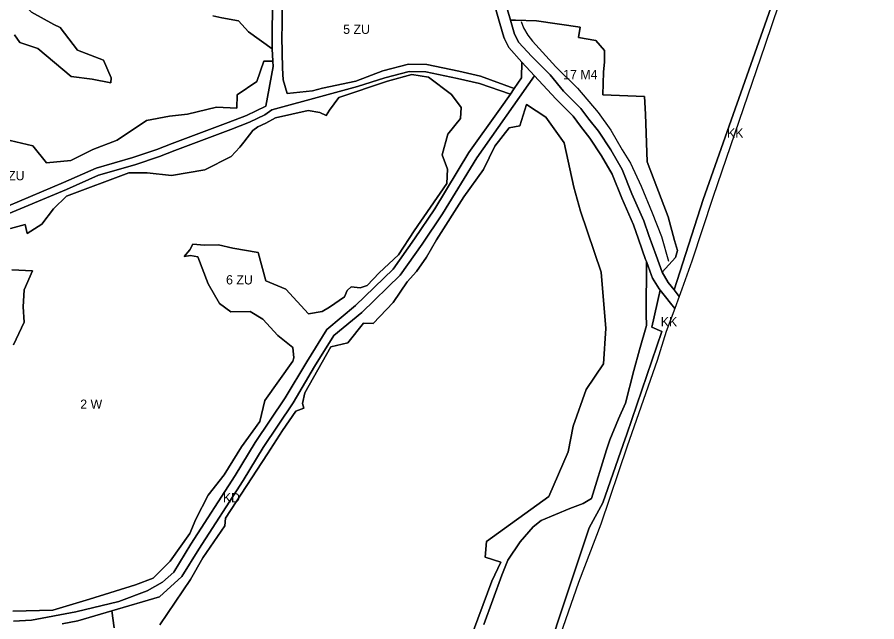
# Model space of a CAD drawing. Extents: x 7437831 to 7440315, y 5545798 to 5547888.
# Drawn here: x 7439385 to 7440315, y 5546197 to 5546851 of the extents above; entities that cross this region are included whole.
import ezdxf

# ---------------------------------------------------------------- set-up
doc = ezdxf.new("R2010")
doc.units = 0
for name, color, linetype in [('linie_rozgraniczajace', 7, 'Continuous'), ('linie_zabudowy_nieprzekraczalne', 7, 'Continuous'), ('oznaczenia_przeznaczen', 7, 'Continuous')]:
    doc.layers.add(name, color=color, linetype=linetype)

msp = doc.modelspace()

# ---------------------------------------------------------------- linework, layer by layer
at = {"layer": 'linie_rozgraniczajace'}
for points in [[(7440308.05, 5547177.94), (7440315.29, 5547171.09), (7440256.26, 5546998.43), (7440230.77, 5546929.2), (7440194.34, 5546821.2), (7440137.83, 5546655.9), (7440115.26, 5546587.11), (7440104.3, 5546556.76), (7440101.52, 5546548.77), (7440096.01, 5546555.84), (7440127.28, 5546653.58), (7440200.75, 5546860.84)], [(7439918.8, 5546847.65), (7439924.22, 5546847.6), (7439947.11, 5546846.82), (7439994.18, 5546840.04), (7439992.52, 5546828.97), (7440011.09, 5546825.6), (7440020.73, 5546814.89), (7440020.47, 5546802.43), (7440019.46, 5546791.36), (7440018.71, 5546766.87), (7440064.01, 5546765.21), (7440064.91, 5546745.98), (7440066.91, 5546694.54), (7440089.6, 5546635.12), (7440096.53, 5546609.5), (7440099.68, 5546598.47), (7440097.3, 5546591.13), (7440082.84, 5546574.93), (7440076.45, 5546592.96), (7440068.57, 5546614.77), (7440063.17, 5546630.62), (7440050.2, 5546659.93), (7440039.6, 5546686.31), (7440027.44, 5546707.26), (7440014.28, 5546727.5), (7440003.83, 5546740.49), (7439995.16, 5546752.12), (7439976.38, 5546771), (7439961.64, 5546788.64), (7439941.49, 5546808.71), (7439927.82, 5546823.37), (7439923.29, 5546832.62)]]:
    msp.add_lwpolyline(points, close=True, dxfattribs=at)
for points in [[(7439486.82, 5546785.36), (7439478.44, 5546804.23), (7439450.21, 5546815.29), (7439431.59, 5546839.56), (7439424.64, 5546843.02), (7439400.36, 5546856.35), (7439385.83, 5546872.11), (7439401.24, 5546882.58), (7439408.98, 5546907.43), (7439402.67, 5546916.88), (7439385.28, 5546930.1), (7439387.21, 5546943.73), (7439385.76, 5546947.44), (7439390.7, 5546965.05)], [(7439381.22, 5546942.02), (7439385.76, 5546947.44), (7439387.21, 5546943.73), (7439385.28, 5546930.1), (7439402.67, 5546916.88), (7439408.98, 5546907.43), (7439401.24, 5546882.58), (7439385.83, 5546872.11), (7439400.36, 5546856.35), (7439424.64, 5546843.02), (7439431.59, 5546839.56), (7439450.21, 5546815.29), (7439478.44, 5546804.23), (7439486.82, 5546785.36), (7439486.23, 5546779.85), (7439466.03, 5546783.83), (7439443.54, 5546786.77), (7439407.4, 5546817.11), (7439388.08, 5546823.63), (7439382.15, 5546831.69)], [(7439363.32, 5546641.95), (7439435.2, 5546672.02), (7439470.38, 5546687.44), (7439510.11, 5546699), (7439536.19, 5546707.81), (7439552.73, 5546714.25), (7439613.29, 5546736.86), (7439633.09, 5546744.54), (7439654.12, 5546754.75), (7439662.13, 5546797.65), (7439661.78, 5546803.45), (7439661, 5546816.56), (7439661.34, 5546878.71)], [(7439671.37, 5546879.16), (7439671.77, 5546841.75), (7439671.4, 5546829.71), (7439672.18, 5546795.77), (7439673.06, 5546783.17), (7439677.12, 5546768.28), (7439704.72, 5546771.38), (7439715.53, 5546774.01), (7439751.52, 5546781.59), (7439780.57, 5546793.02), (7439808.46, 5546800.07), (7439828.33, 5546799.8), (7439863.08, 5546792.42), (7439886.49, 5546787.27), (7439922.97, 5546773.92), (7439918.72, 5546767.8), (7439885.39, 5546779.32), (7439861.38, 5546784.6), (7439827.44, 5546791.81), (7439809.4, 5546792.06), (7439782.77, 5546785.32), (7439753.23, 5546775.91), (7439717.62, 5546766.29), (7439660.5, 5546750.58), (7439653.17, 5546745.39), (7439636.29, 5546737.2), (7439616.14, 5546729.39), (7439555.58, 5546706.77), (7439538.92, 5546700.29), (7439512.51, 5546691.36), (7439473.11, 5546679.9), (7439438.35, 5546664.67), (7439366.32, 5546634.53)], [(7439661.34, 5546878.71), (7439661, 5546816.56), (7439635.43, 5546835.19), (7439624.57, 5546847.09), (7439606.57, 5546850.24), (7439596.81, 5546852.25)], [(7439903.09, 5546859.16), (7439907.31, 5546844.22), (7439911.79, 5546829.19), (7439912.51, 5546827.34), (7439917.04, 5546818.09), (7439931.02, 5546802.34), (7439930.83, 5546785.24), (7439922.97, 5546773.92), (7439886.49, 5546787.27), (7439863.08, 5546792.42), (7439828.33, 5546799.8), (7439808.46, 5546800.07), (7439780.57, 5546793.02), (7439751.52, 5546781.59), (7439715.53, 5546774.01), (7439704.72, 5546771.38), (7439677.12, 5546768.28), (7439673.06, 5546783.17), (7439672.18, 5546795.77), (7439671.4, 5546829.71), (7439671.77, 5546841.75), (7439671.37, 5546879.16)], [(7439596.81, 5546852.25), (7439606.57, 5546850.24), (7439624.57, 5546847.09), (7439635.43, 5546835.19), (7439661, 5546816.56), (7439661.78, 5546803.45), (7439651.83, 5546803.38), (7439644.33, 5546781.26), (7439623.01, 5546766.92), (7439622.81, 5546752.31), (7439600.71, 5546753.63), (7439569.33, 5546746.09), (7439549.86, 5546743.89), (7439525.1, 5546739.11), (7439493.26, 5546717.83), (7439466.82, 5546707.92), (7439443.08, 5546695.91), (7439416.71, 5546693.37), (7439401.89, 5546711.77), (7439377.63, 5546717.6)], [(7439915.58, 5546858.94), (7439918.8, 5546847.65), (7439923.29, 5546832.62), (7439927.82, 5546823.37), (7439941.49, 5546808.71), (7439961.64, 5546788.64), (7439976.38, 5546771), (7439995.16, 5546752.12), (7440003.83, 5546740.49), (7440014.28, 5546727.5), (7440027.44, 5546707.26), (7440039.6, 5546686.31), (7440050.2, 5546659.93), (7440063.17, 5546630.62), (7440068.57, 5546614.77), (7440076.45, 5546592.96), (7440082.84, 5546574.93), (7440089.68, 5546563.94), (7440096.01, 5546555.84), (7440101.52, 5546548.77), (7440096.72, 5546535.85), (7440092.06, 5546541.39), (7440086.55, 5546548.45), (7440080.94, 5546555.64), (7440079.86, 5546557.08), (7440072.65, 5546568.58), (7440071.34, 5546571.44), (7440065.9, 5546586.8), (7440065.16, 5546588.89), (7440057.29, 5546610.7), (7440051.98, 5546626.25), (7440039.23, 5546655.08), (7440028.79, 5546681.04), (7440017.21, 5546700.97), (7440004.88, 5546719.95), (7439994.49, 5546732.96), (7439986.65, 5546743.66), (7439967.87, 5546762.54), (7439944.92, 5546787.32), (7439931.02, 5546802.34), (7439917.04, 5546818.09), (7439912.51, 5546827.34), (7439911.79, 5546829.19), (7439907.31, 5546844.22), (7439903.09, 5546859.16)], [(7440200.75, 5546860.84), (7440127.28, 5546653.58), (7440096.01, 5546555.84), (7440089.68, 5546563.94), (7440082.84, 5546574.93), (7440097.3, 5546591.13), (7440099.68, 5546598.47), (7440096.53, 5546609.5), (7440089.6, 5546635.12), (7440066.91, 5546694.54), (7440064.91, 5546745.98), (7440064.01, 5546765.21), (7440018.71, 5546766.87), (7440019.46, 5546791.36), (7440020.47, 5546802.43), (7440020.73, 5546814.89), (7440011.09, 5546825.6), (7439992.52, 5546828.97), (7439994.18, 5546840.04), (7439947.11, 5546846.82), (7439924.22, 5546847.6), (7439918.8, 5546847.65), (7439915.58, 5546858.94)], [(7439382.15, 5546831.69), (7439388.08, 5546823.63), (7439407.4, 5546817.11), (7439443.54, 5546786.77), (7439466.03, 5546783.83), (7439486.23, 5546779.85), (7439486.82, 5546785.36)], [(7439377.63, 5546717.6), (7439401.89, 5546711.77), (7439416.71, 5546693.37), (7439443.08, 5546695.91), (7439466.82, 5546707.92), (7439493.26, 5546717.83), (7439525.1, 5546739.11), (7439549.86, 5546743.89), (7439569.33, 5546746.09), (7439600.71, 5546753.63), (7439622.81, 5546752.31), (7439623.01, 5546766.92), (7439644.33, 5546781.26), (7439651.83, 5546803.38), (7439661.78, 5546803.45), (7439662.13, 5546797.65), (7439654.12, 5546754.75), (7439633.09, 5546744.54), (7439613.29, 5546736.86), (7439552.73, 5546714.25), (7439536.19, 5546707.81), (7439510.11, 5546699), (7439470.38, 5546687.44), (7439435.2, 5546672.02), (7439363.32, 5546641.95)], [(7439380.94, 5546197.47), (7439400.62, 5546198.75), (7439448.52, 5546207.84), (7439495.02, 5546219.05), (7439525.63, 5546230.47), (7439542.17, 5546239.93), (7439554.55, 5546250.62), (7439573.14, 5546280.84), (7439621.09, 5546355.07), (7439642.72, 5546390.77), (7439675.08, 5546439.03), (7439698.39, 5546478.28), (7439720.08, 5546513.24), (7439751.29, 5546539.09), (7439792.03, 5546578.22), (7439814.95, 5546611.06), (7439836.9, 5546643.49), (7439873.96, 5546704.41), (7439907.41, 5546751.52), (7439918.72, 5546767.8), (7439922.97, 5546773.92), (7439930.83, 5546785.24), (7439931.02, 5546802.34), (7439944.92, 5546787.32), (7439882.31, 5546698.91), (7439845.31, 5546638.09), (7439823.19, 5546605.4), (7439799.67, 5546571.7), (7439757.95, 5546531.62), (7439727.72, 5546506.58), (7439706.94, 5546473.09), (7439683.54, 5546433.69), (7439651.15, 5546385.39), (7439629.56, 5546349.77), (7439581.6, 5546275.5), (7439563.31, 5546245.78), (7439539.14, 5546224.11), (7439487.44, 5546208.89), (7439450.62, 5546198.06), (7439433.75, 5546194.86)], [(7439366.32, 5546634.53), (7439438.35, 5546664.67), (7439473.11, 5546679.9), (7439512.51, 5546691.36), (7439538.92, 5546700.29), (7439555.58, 5546706.77), (7439616.14, 5546729.39), (7439636.29, 5546737.2), (7439653.17, 5546745.39), (7439660.5, 5546750.58), (7439717.62, 5546766.29), (7439753.23, 5546775.91), (7439782.77, 5546785.32), (7439809.4, 5546792.06), (7439827.44, 5546791.81), (7439861.38, 5546784.6), (7439885.39, 5546779.32), (7439918.72, 5546767.8), (7439907.41, 5546751.52), (7439873.96, 5546704.41), (7439836.9, 5546643.49), (7439814.95, 5546611.06), (7439792.03, 5546578.22), (7439751.29, 5546539.09), (7439720.08, 5546513.24), (7439698.39, 5546478.28), (7439675.08, 5546439.03), (7439642.72, 5546390.77), (7439621.09, 5546355.07), (7439573.14, 5546280.84), (7439554.55, 5546250.62), (7439542.17, 5546239.93), (7439525.63, 5546230.47), (7439495.02, 5546219.05), (7439448.52, 5546207.84), (7439400.62, 5546198.75), (7439380.94, 5546197.47)], [(7439854.94, 5546767.31), (7439829.99, 5546786.14), (7439812.14, 5546788.85), (7439785.73, 5546781.58), (7439733.11, 5546763.89), (7439723.11, 5546750.4), (7439719.31, 5546744.42), (7439712.48, 5546747.88), (7439700.05, 5546749.8), (7439664.46, 5546742.01), (7439654.25, 5546736.22), (7439645.44, 5546732.23), (7439640.09, 5546728.4), (7439630.22, 5546715.54), (7439625.85, 5546710.21), (7439616.78, 5546700.12), (7439588.12, 5546685.96), (7439552.05, 5546679.57), (7439525.86, 5546682.66), (7439506.01, 5546682.43), (7439438.29, 5546657.31), (7439424.49, 5546643.76), (7439411.74, 5546627.05), (7439395.98, 5546616.82), (7439393.73, 5546626.76), (7439377.82, 5546622.48)], [(7439654.25, 5546736.22), (7439664.46, 5546742.01), (7439700.05, 5546749.8), (7439712.48, 5546747.88), (7439719.31, 5546744.42), (7439723.11, 5546750.4), (7439733.11, 5546763.89), (7439785.73, 5546781.58), (7439812.14, 5546788.85), (7439829.99, 5546786.14), (7439854.94, 5546767.31), (7439865.39, 5546753.05), (7439864.65, 5546741.39), (7439850.93, 5546724.3), (7439844.77, 5546702), (7439850.54, 5546686.56), (7439849.95, 5546670.96), (7439814.52, 5546619.84), (7439797.76, 5546593.98), (7439776.69, 5546574.39), (7439763.82, 5546560.75), (7439756.21, 5546558.2), (7439746.55, 5546559.29), (7439742.26, 5546555.36), (7439739.41, 5546548.45), (7439723, 5546537.34), (7439715.03, 5546532.67), (7439700.14, 5546530.18), (7439675.72, 5546556.88), (7439654.05, 5546565.6), (7439645.85, 5546596.41), (7439618.28, 5546601.15), (7439603, 5546604.77), (7439587.65, 5546604.19), (7439575.25, 5546605.29), (7439571.74, 5546599.27), (7439565.85, 5546592.14), (7439572.75, 5546593.24), (7439580.43, 5546591.53), (7439591.85, 5546562.44), (7439603.95, 5546541.22), (7439616.1, 5546532.37), (7439637.28, 5546532.49), (7439650.84, 5546524.37), (7439666.99, 5546506.61), (7439683.27, 5546493.77), (7439684.46, 5546482.5), (7439683.29, 5546478.67), (7439653.2, 5546436.29), (7439647.48, 5546413.73), (7439627.89, 5546386.15), (7439608.9, 5546355.91), (7439591.6, 5546334.01), (7439578.21, 5546307.89), (7439571.85, 5546292.55), (7439550.5, 5546262.35), (7439532.26, 5546243.99), (7439513.25, 5546237), (7439463.2, 5546221.29), (7439423.56, 5546209.6), (7439380.47, 5546208.46)], [(7439490.15, 5546190.37), (7439487.44, 5546208.89), (7439539.14, 5546224.11), (7439563.31, 5546245.78), (7439581.6, 5546275.5), (7439629.56, 5546349.77), (7439651.15, 5546385.39), (7439683.54, 5546433.69), (7439706.94, 5546473.09), (7439727.72, 5546506.58), (7439757.95, 5546531.62), (7439799.67, 5546571.7), (7439823.19, 5546605.4), (7439845.31, 5546638.09), (7439882.31, 5546698.91), (7439944.92, 5546787.32), (7439967.87, 5546762.54), (7439986.65, 5546743.66), (7439994.49, 5546732.96), (7440004.88, 5546719.95), (7440017.21, 5546700.97), (7440028.79, 5546681.04), (7440039.23, 5546655.08), (7440051.98, 5546626.25), (7440057.29, 5546610.7), (7440065.16, 5546588.89), (7440065.9, 5546586.8), (7440065.64, 5546529.24), (7440066.09, 5546517.44), (7440058.48, 5546491.13), (7440052.26, 5546468.9), (7440043.46, 5546433.25), (7440035.75, 5546416.29), (7440026.32, 5546393.84), (7440022.68, 5546382.78), (7440006.48, 5546330.28), (7439997.59, 5546324.73), (7439982.99, 5546319.3), (7439952.11, 5546306.67), (7439943.44, 5546299.82), (7439929.41, 5546283.59), (7439915.91, 5546263.73), (7439909.44, 5546247.36), (7439890.04, 5546194.08)], [(7439380.47, 5546208.46), (7439423.56, 5546209.6), (7439463.2, 5546221.29), (7439513.25, 5546237), (7439532.26, 5546243.99), (7439550.5, 5546262.35), (7439571.85, 5546292.55), (7439578.21, 5546307.89), (7439591.6, 5546334.01), (7439608.9, 5546355.91), (7439627.89, 5546386.15), (7439647.48, 5546413.73), (7439653.2, 5546436.29), (7439683.29, 5546478.67), (7439684.46, 5546482.5), (7439683.27, 5546493.77), (7439666.99, 5546506.61), (7439650.84, 5546524.37), (7439637.28, 5546532.49), (7439616.1, 5546532.37), (7439603.95, 5546541.22), (7439591.85, 5546562.44), (7439580.43, 5546591.53), (7439572.75, 5546593.24), (7439565.85, 5546592.14), (7439571.74, 5546599.27), (7439575.25, 5546605.29), (7439587.65, 5546604.19), (7439603, 5546604.77), (7439618.28, 5546601.15), (7439645.85, 5546596.41), (7439654.05, 5546565.6), (7439675.72, 5546556.88), (7439700.14, 5546530.18), (7439715.03, 5546532.67), (7439723, 5546537.34), (7439739.41, 5546548.45), (7439742.26, 5546555.36), (7439746.55, 5546559.29), (7439756.21, 5546558.2), (7439763.82, 5546560.75), (7439776.69, 5546574.39), (7439797.76, 5546593.98), (7439814.52, 5546619.84), (7439849.95, 5546670.96), (7439850.54, 5546686.56), (7439844.77, 5546702), (7439850.93, 5546724.3), (7439864.65, 5546741.39), (7439865.39, 5546753.05), (7439854.94, 5546767.31)], [(7439936.27, 5546756.48), (7439929, 5546733.23), (7439917.5, 5546731.3), (7439902.1, 5546711.37), (7439889.72, 5546686.22), (7439868.39, 5546656.55), (7439838.88, 5546610.11), (7439827.86, 5546591.28), (7439817.11, 5546575.85), (7439807.17, 5546564.5), (7439792.08, 5546542.23), (7439770.26, 5546519.49), (7439759.83, 5546519.96), (7439743, 5546498.56), (7439724.61, 5546494.41), (7439696.47, 5546444.65), (7439693.93, 5546433.16), (7439695.32, 5546427.89), (7439686.58, 5546424.93), (7439672.06, 5546403.86), (7439655.91, 5546378.67), (7439610.32, 5546309.18), (7439609.75, 5546300.73), (7439585.86, 5546266.14), (7439572.52, 5546242.78), (7439539.47, 5546193.7)], [(7439936.27, 5546756.48), (7439957.3, 5546742.71), (7439976.97, 5546715.12), (7439987.59, 5546667.07), (7439994.76, 5546640.93), (7440016.97, 5546575.06), (7440021.88, 5546514.27), (7440019.37, 5546476.05), (7440000.66, 5546448.3), (7439986.83, 5546408.43), (7439981.12, 5546380.88), (7439960.5, 5546332.44), (7439892.91, 5546283.88), (7439891.56, 5546267), (7439908.37, 5546261.42), (7439898.74, 5546241.04), (7439874.23, 5546174.75)], [(7439902.1, 5546711.37), (7439917.5, 5546731.3), (7439929, 5546733.23), (7439936.27, 5546756.48)], [(7439987.59, 5546667.07), (7439976.97, 5546715.12), (7439957.3, 5546742.71), (7439936.27, 5546756.48)], [(7439377.82, 5546622.48), (7439393.73, 5546626.76), (7439395.98, 5546616.82), (7439411.74, 5546627.05), (7439424.49, 5546643.76), (7439438.29, 5546657.31), (7439506.01, 5546682.43), (7439525.86, 5546682.66), (7439552.05, 5546679.57), (7439588.12, 5546685.96), (7439616.78, 5546700.12), (7439625.85, 5546710.21), (7439630.22, 5546715.54), (7439640.09, 5546728.4), (7439645.44, 5546732.23), (7439654.25, 5546736.22)], [(7439539.47, 5546193.7), (7439572.52, 5546242.78), (7439585.86, 5546266.14), (7439609.75, 5546300.73), (7439610.32, 5546309.18), (7439655.91, 5546378.67), (7439672.06, 5546403.86), (7439686.58, 5546424.93), (7439695.32, 5546427.89), (7439693.93, 5546433.16), (7439696.47, 5546444.65), (7439724.61, 5546494.41), (7439743, 5546498.56), (7439759.83, 5546519.96), (7439770.26, 5546519.49), (7439792.08, 5546542.23), (7439807.17, 5546564.5), (7439817.11, 5546575.85), (7439827.86, 5546591.28), (7439838.88, 5546610.11), (7439868.39, 5546656.55), (7439889.72, 5546686.22), (7439902.1, 5546711.37)], [(7439874.23, 5546174.75), (7439898.74, 5546241.04), (7439908.37, 5546261.42), (7439891.56, 5546267), (7439892.91, 5546283.88), (7439960.5, 5546332.44), (7439981.12, 5546380.88), (7439986.83, 5546408.43), (7440000.66, 5546448.3), (7440019.37, 5546476.05), (7440021.88, 5546514.27), (7440016.97, 5546575.06), (7439994.76, 5546640.93), (7439987.59, 5546667.07)], [(7440065.9, 5546586.8), (7440071.34, 5546571.44), (7440072.65, 5546568.58), (7440079.86, 5546557.08), (7440080.94, 5546555.64), (7440071.86, 5546515.79), (7440082.67, 5546510.79), (7440044.68, 5546400.01), (7440040.64, 5546388.84), (7440018.65, 5546325.46), (7440004.11, 5546298.64), (7440003.11, 5546295.44), (7439970.26, 5546197.06), (7439927.82, 5546065.29)], [(7439982.99, 5546319.3), (7439997.59, 5546324.73), (7440006.48, 5546330.28), (7440022.68, 5546382.78), (7440026.32, 5546393.84), (7440035.75, 5546416.29), (7440043.46, 5546433.25), (7440052.26, 5546468.9), (7440058.48, 5546491.13), (7440066.09, 5546517.44), (7440065.64, 5546529.24), (7440065.9, 5546586.8)], [(7439379.25, 5546577.57), (7439401.45, 5546576.44), (7439392.44, 5546556.16), (7439391.49, 5546537.66), (7439392.56, 5546521.09), (7439380.9, 5546496.43)], [(7439380.9, 5546496.43), (7439392.56, 5546521.09), (7439391.49, 5546537.66), (7439392.44, 5546556.16), (7439401.45, 5546576.44), (7439379.25, 5546577.57)], [(7439927.82, 5546065.29), (7439970.26, 5546197.06), (7440003.11, 5546295.44), (7440004.11, 5546298.64), (7440018.65, 5546325.46), (7440040.64, 5546388.84), (7440044.68, 5546400.01), (7440082.67, 5546510.79), (7440071.86, 5546515.79), (7440080.94, 5546555.64), (7440086.55, 5546548.45), (7440092.06, 5546541.39), (7440096.72, 5546535.85), (7440087.49, 5546510.95), (7440077.43, 5546479.51), (7440045.1, 5546387.01), (7440016.55, 5546302.61), (7439992.38, 5546239.53), (7439967.33, 5546166.94)], [(7439890.04, 5546194.08), (7439909.44, 5546247.36), (7439915.91, 5546263.73), (7439929.41, 5546283.59), (7439943.44, 5546299.82), (7439952.11, 5546306.67), (7439982.99, 5546319.3)], [(7439433.75, 5546194.86), (7439450.62, 5546198.06), (7439487.44, 5546208.89), (7439490.15, 5546190.37)]]:
    msp.add_lwpolyline(points, dxfattribs=at)
at = {"layer": 'linie_zabudowy_nieprzekraczalne'}
msp.add_lwpolyline([(7439930.37, 5546846.28), (7439932.91, 5546839.37), (7439937.53, 5546831.26), (7439942.86, 5546824.88), (7439968.07, 5546797.34), (7439991.41, 5546774.18), (7440013.91, 5546747.71), (7440027.42, 5546728.75), (7440039.8, 5546707.3), (7440048.63, 5546693.14), (7440060.24, 5546667.97), (7440072.28, 5546639.37), (7440082.23, 5546613.51), (7440089.88, 5546586.86)], dxfattribs=at)

# ---------------------------------------------------------------- texts
at = {"layer": 'oznaczenia_przeznaczen'}
for s, p in [('5 ZU', (7439737.8453, 5546832.83)), ('17 M4', (7439975.8605, 5546783.84)), ('KK', (7440153.1179, 5546720.58)), ('3 ZU', (7439364.0253, 5546674.47)), ('6 ZU', (7439611.0653, 5546561.84)), ('KK', (7440081.4079, 5546516.43)), ('2 W', (7439453.2743, 5546427.3)), ('KD', (7439607.5827, 5546326.23))]:
    msp.add_text(s, height=10, dxfattribs=at).set_placement(p)

doc.saveas('drawing.dxf')
